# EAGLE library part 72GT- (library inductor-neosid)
FILTER dual helix bandpass filter with tab, type G
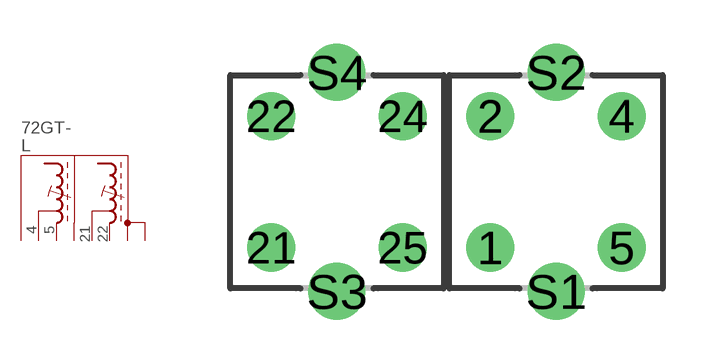
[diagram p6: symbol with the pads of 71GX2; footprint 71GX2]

Designator prefix L

## 72GT-452122 (OC_FARNELL: unknown; OC_NEWARK: unknown)  [71GX2]
4  IN  pas
5  GND1  pas
21  OUT  pas
22  GND2  pas
S1  S1  pas
S2  S2  pas
S3  S3  pas
S4  S4  pas

## 72GT-422122 (OC_FARNELL: unknown; OC_NEWARK: unknown)  [71GX2]
2  GND1  pas
4  IN  pas
21  OUT  pas
22  GND2  pas
S1  S1  pas
S2  S2  pas
S3  S3  pas
S4  S4  pas

## 72GT-512224 (OC_FARNELL: unknown; OC_NEWARK: unknown)  [71GX2]
1  GND1  pas
5  IN  pas
22  OUT  pas
24  GND2  pas
S1  S1  pas
S2  S2  pas
S3  S3  pas
S4  S4  pas

## 72GT-512122 (OC_FARNELL: unknown; OC_NEWARK: unknown)  [71GX2]
Pads as for 71GX2

## 72GT-542122 (OC_FARNELL: unknown; OC_NEWARK: unknown)  [71GX2]
4  GND1  pas
5  IN  pas
21  OUT  pas
22  GND2  pas
S1  S1  pas
S2  S2  pas
S3  S3  pas
S4  S4  pas

## Footprint 71GX2 (pad centres in mm)
DUAL RF COIL ASSEMBLY 1 winding, 4 pads, grid 2.25 mm
drill 1.1 round: 1 1.5,-2.25; 2 1.5,2.25; 4 6,2.25; 5 6,-2.25; 21 -6,-2.25; 22 -6,2.25; 24 -1.5,2.25; 25 -1.5,-2.25
drill 1.3 round: S1 3.75,-3.75; S2 3.75,3.75; S3 -3.75,-3.75; S4 -3.75,3.75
